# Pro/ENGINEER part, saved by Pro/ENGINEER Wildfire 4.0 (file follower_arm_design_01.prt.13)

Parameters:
  METRIC = "NO"

Other parameters: PITCH, DRILL_DIAMETER, THREAD_DIAMETER, THREADS_PER_INCH, THREAD_DEPTH, THREAD_LENGTH, DRILL_POINT_ANGLE, DRILL_DEPTH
